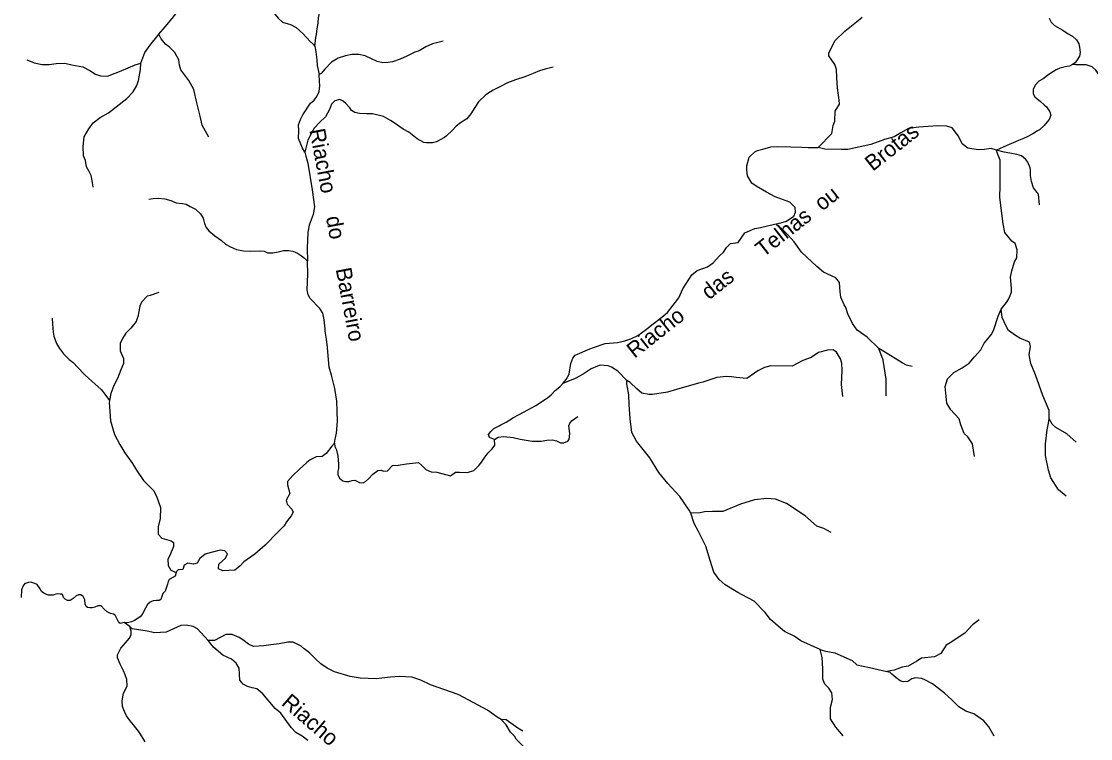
# Model space of a CAD drawing. Extents: x 717.8 to 772.7, y 8672.2 to 8728.
# Drawn here: x 731.77 to 745.36, y 8693.87 to 8702.99 of the extents above; entities that cross this region are included whole.
import ezdxf
from ezdxf.enums import TextEntityAlignment as Align

# ---------------------------------------------------------------- set-up
doc = ezdxf.new("R2010")
doc.units = 0
doc.header["$LTSCALE"] = 0.08
doc.linetypes.add('LONG_DASHED', pattern=[7.5, 6, -1.5])
doc.layers.add('61', color=7, linetype='Continuous')
doc.layers.add('9', color=7, linetype='LONG_DASHED', lineweight=25)

msp = doc.modelspace()

# ---------------------------------------------------------------- linework, layer by layer
at = {"layer": '9'}
msp.add_line((733.1514, 8695.2936), (733.0803, 8695.3465), dxfattribs=at)
for points in [[(734.3526, 8703.6392), (734.4907, 8703.6359), (734.5619, 8703.6114), (734.6403, 8703.5631), (734.6934, 8703.4998), (734.7153, 8703.458), (734.748, 8703.3878), (734.7584, 8703.3394), (734.7952, 8703.2871), (734.8925, 8703.2294), (734.9722, 8703.1152), (734.999, 8703.074), (735.0368, 8703.0274), (735.0933, 8702.9779), (735.1917, 8702.9464), (735.2674, 8702.9086), (735.3517, 8702.8327), (735.4443, 8702.732), (735.485, 8702.6924), (735.5037, 8702.6658)], [(733.5186, 8702.8226), (733.5988, 8702.9187), (733.6899, 8703.0208), (733.7896, 8703.1523), (733.8096, 8703.2191), (733.8242, 8703.2836), (733.8553, 8703.3552), (733.8781, 8703.4006), (733.8984, 8703.4386)], [(735.5037, 8702.6658), (735.5152, 8702.7801), (735.5234, 8702.8207), (735.5272, 8702.8636), (735.5439, 8702.9663), (735.5511, 8703.0307), (735.5654, 8703.1071), (735.575, 8703.1668), (735.5893, 8703.2169)], [(741.9017, 8701.382), (742.073, 8701.5613), (742.0908, 8701.6619), (742.1132, 8701.7189), (742.1183, 8701.8464), (742.1712, 8701.9324), (742.1677, 8701.9855), (742.1445, 8702.1431), (742.1393, 8702.2679), (742.1346, 8702.3753), (742.1111, 8702.4397), (742.038, 8702.5475), (742.0381, 8702.5881), (742.1166, 8702.7432), (742.2394, 8702.862), (742.3859, 8702.9814), (742.4606, 8703.0389)], [(744.8368, 8703.0256), (744.8631, 8702.9778), (744.906, 8702.9348), (745.011, 8702.8764), (745.0777, 8702.8287), (745.1325, 8702.8001), (745.185, 8702.7522), (745.2136, 8702.6998), (745.2232, 8702.6592), (745.2304, 8702.5923), (745.2233, 8702.5422), (745.1924, 8702.4967), (745.1663, 8702.4609), (745.1353, 8702.437)], [(733.2909, 8702.4534), (733.343, 8702.591), (733.386, 8702.652), (733.4204, 8702.7006), (733.494, 8702.7882), (733.5186, 8702.8226)], [(734.1573, 8701.5136), (734.0718, 8701.667), (734.0433, 8701.7806), (734.0034, 8701.951), (733.9636, 8702.1214), (733.9009, 8702.235), (733.7984, 8702.3714), (733.7813, 8702.4282), (733.7756, 8702.4964), (733.722, 8702.5898), (733.6522, 8702.6621), (733.6063, 8702.6981), (733.5491, 8702.7653), (733.5186, 8702.8226)], [(735.5037, 8702.6658), (735.5049, 8702.651), (735.5142, 8702.6003), (735.5274, 8702.4989), (735.5329, 8702.4256), (735.5561, 8702.3102)], [(737.1338, 8702.7343), (736.9964, 8702.7011), (736.9143, 8702.6606), (736.8287, 8702.6125), (736.7741, 8702.5945), (736.6733, 8702.543), (736.5854, 8702.5042), (736.4916, 8702.4721), (736.4363, 8702.4617), (736.368, 8702.4573), (736.296, 8702.4756), (736.2226, 8702.51), (736.143, 8702.5484), (736.0625, 8702.5646), (735.9714, 8702.5646), (735.891, 8702.5486), (735.7999, 8702.5165), (735.7141, 8702.4684)], [(731.8406, 8702.4992), (731.9369, 8702.4613), (732.0387, 8702.4374), (732.1261, 8702.4402), (732.2148, 8702.4528), (732.3233, 8702.4546), (732.4142, 8702.4357), (732.5518, 8702.4102), (732.6419, 8702.3616), (732.716, 8702.3161), (732.7789, 8702.2923), (732.8677, 8702.2909), (732.9666, 8702.3271), (733.0209, 8702.3488), (733.0998, 8702.3836), (733.2204, 8702.4344), (733.2909, 8702.4534)], [(732.6857, 8700.8783), (732.6714, 8700.9648), (732.6591, 8701.0272), (732.6339, 8701.0763), (732.6016, 8701.1389), (732.5858, 8701.2184), (732.5624, 8701.2766), (732.56, 8701.3963), (732.5722, 8701.5169), (732.6302, 8701.6216), (732.6862, 8701.6973), (732.7727, 8701.7651), (732.8808, 8701.8258), (733.1145, 8702.0073), (733.1942, 8702.0923), (733.2414, 8702.1698), (733.2626, 8702.2342), (733.2853, 8702.3742), (733.2909, 8702.4534)], [(738.5331, 8702.4024), (738.4288, 8702.3773), (738.3593, 8702.3558), (738.279, 8702.3237), (738.172, 8702.2808), (738.0544, 8702.2433), (737.9527, 8702.2057), (737.8618, 8702.1575), (737.7676, 8702.1114), (737.7337, 8702.0905), (737.6783, 8702.0539), (737.582, 8701.963), (737.5359, 8701.8932), (737.4865, 8701.8099), (737.4345, 8701.7462), (737.356, 8701.6974), (737.3001, 8701.6531), (737.2543, 8701.6026), (737.1759, 8701.5311), (737.1504, 8701.5095), (737.0501, 8701.4566), (736.9965, 8701.4441), (736.9219, 8701.4426), (736.8878, 8701.4465), (736.8016, 8701.4938), (736.6975, 8701.5762), (736.626, 8701.6174), (736.5103, 8701.6974), (736.463, 8701.7261), (736.3738, 8701.7768), (736.2343, 8701.8095), (736.1647, 8701.8096), (736.0717, 8701.8138), (736.0104, 8701.827), (735.97, 8701.8551), (735.9475, 8701.8892), (735.8986, 8701.9404), (735.8644, 8701.9738), (735.8225, 8701.9924), (735.7581, 8701.9745), (735.7162, 8701.9333), (735.6912, 8701.8674), (735.6369, 8701.7727), (735.5662, 8701.7066), (735.4938, 8701.6282), (735.473, 8701.5905), (735.4129, 8701.4761), (735.3764, 8701.3226)], [(735.7141, 8702.4684), (735.6282, 8702.3775), (735.5846, 8702.3255), (735.5561, 8702.3102)], [(745.1353, 8702.437), (745.0964, 8702.4182), (745.04, 8702.4098), (744.9715, 8702.39), (744.9266, 8702.3687), (744.8923, 8702.3481), (744.8314, 8702.3108), (744.7616, 8702.2578), (744.7045, 8702.2242), (744.664, 8702.1789), (744.6316, 8702.1246), (744.6331, 8702.0667), (744.6552, 8702.0264), (744.7264, 8701.9675), (744.7741, 8701.9246), (744.8037, 8701.9014), (744.8456, 8701.8374), (744.857, 8701.7948), (744.8387, 8701.7407), (744.8128, 8701.7087), (744.7725, 8701.6607), (744.7126, 8701.6069), (744.6872, 8701.5936), (744.6301, 8701.5578), (744.5592, 8701.519), (744.512, 8701.4984), (744.4488, 8701.4731), (744.4083, 8701.4563), (744.2991, 8701.4066), (744.1662, 8701.348)], [(745.5158, 8702.2419), (745.488, 8702.2772), (745.4514, 8702.3382), (745.4285, 8702.3657), (745.3813, 8702.4083), (745.3059, 8702.4335), (745.2806, 8702.4323), (745.221, 8702.4346), (745.1758, 8702.4346), (745.1353, 8702.437)], [(735.3764, 8701.3226), (735.3477, 8701.3732), (735.2965, 8701.4982), (735.2983, 8701.601), (735.2968, 8701.6699), (735.321, 8701.7372), (735.3497, 8701.7989), (735.4487, 8701.9448), (735.4941, 8701.983), (735.5299, 8702.0307), (735.5585, 8702.0928), (735.5656, 8702.1668), (735.5607, 8702.2265), (735.5561, 8702.3102)], [(744.1662, 8701.348), (744.1001, 8701.3702), (744.0112, 8701.3561), (743.9343, 8701.355), (743.8042, 8701.3756), (743.7305, 8701.4309), (743.6828, 8701.5276), (743.6047, 8701.6315), (743.5354, 8701.6554), (743.4205, 8701.6586), (743.3002, 8701.6521), (743.1798, 8701.6424), (743.0497, 8701.6228), (742.9511, 8701.5697), (742.8677, 8701.5187), (742.7441, 8701.4829), (742.5717, 8701.4233), (742.3755, 8701.3778), (742.278, 8701.3593), (742.193, 8701.356), (741.9872, 8701.3633), (741.9017, 8701.382)], [(735.3764, 8701.3226), (735.3892, 8701.2736), (735.4148, 8701.1835), (735.4697, 8700.8462), (735.4979, 8700.6298), (735.4825, 8700.5332), (735.4297, 8700.3971), (735.4126, 8700.3064), (735.4068, 8700.0981), (735.4096, 8699.9372)], [(741.3648, 8700.4115), (741.427, 8700.4254), (741.4991, 8700.4471), (741.5911, 8700.5099), (741.6137, 8700.5614), (741.6078, 8700.6199), (741.5389, 8700.687), (741.4475, 8700.721), (741.3523, 8700.7579), (741.2439, 8700.8143), (741.111, 8700.8905), (741.0587, 8700.9304), (741.0008, 8701.0216), (740.9949, 8701.099), (740.9917, 8701.1504), (741.0215, 8701.2603), (741.0971, 8701.328), (741.128, 8701.3435), (741.1987, 8701.3622), (741.3009, 8701.3896), (741.3854, 8701.3964), (741.5521, 8701.3932), (741.692, 8701.387), (741.7727, 8701.3817), (741.829, 8701.3821), (741.9017, 8701.382)], [(744.7119, 8700.6555), (744.7019, 8700.7878), (744.6389, 8700.8724), (744.6121, 8700.95), (744.5994, 8701.0271), (744.5984, 8701.1052), (744.5945, 8701.126), (744.5671, 8701.197), (744.5397, 8701.2311), (744.4861, 8701.2782), (744.4255, 8701.2927), (744.3376, 8701.3113), (744.2661, 8701.3247), (744.1662, 8701.348)], [(744.2261, 8699.3296), (744.2962, 8699.4143), (744.324, 8699.4612), (744.3566, 8699.5427), (744.3596, 8699.5948), (744.3473, 8699.7341), (744.3607, 8699.8174), (744.3981, 8699.9306), (744.4237, 8699.9822), (744.4295, 8700.083), (744.4046, 8700.1632), (744.3639, 8700.1909), (744.272, 8700.3007), (744.2501, 8700.4119), (744.2097, 8700.7486), (744.2148, 8700.8957), (744.2119, 8701.0966), (744.2126, 8701.2236), (744.1816, 8701.3058), (744.1662, 8701.348)], [(733.3918, 8700.7246), (733.448, 8700.7339), (733.5159, 8700.7385), (733.5955, 8700.729), (733.6704, 8700.7078), (733.7384, 8700.6796), (733.8203, 8700.6725), (733.8671, 8700.6631), (733.9186, 8700.6349), (733.9866, 8700.5997), (734.0475, 8700.5386), (734.0826, 8700.4846), (734.0989, 8700.4168), (734.1223, 8700.3675), (734.1574, 8700.3253), (734.2323, 8700.2595), (734.3143, 8700.2009), (734.368, 8700.156), (734.4313, 8700.1188), (734.5062, 8700.0881), (734.5975, 8700.0693), (734.6794, 8700.0645), (734.7954, 8700.0714), (734.8608, 8700.0666), (734.903, 8700.0456), (734.9685, 8700.0431), (735.0387, 8700.0571), (735.1042, 8700.0757), (735.1698, 8700.0757), (735.2236, 8700.0662), (735.282, 8700.0404), (735.3335, 8700.0075), (735.3732, 8699.9747), (735.4096, 8699.9372)], [(738.6562, 8698.3854), (738.6955, 8698.4346), (738.7367, 8698.5035), (738.7566, 8698.6384), (738.7841, 8698.704), (738.8104, 8698.7453), (738.9989, 8698.8256), (739.0452, 8698.8429), (739.1914, 8698.8903), (739.3489, 8698.906), (739.4436, 8698.9263), (739.521, 8698.9528), (739.608, 8698.9933), (739.7009, 8699.0628), (739.8035, 8699.1423), (739.8939, 8699.2096), (739.9834, 8699.2867), (740.1277, 8699.4728), (740.1786, 8699.5878), (740.2951, 8699.7631), (740.3625, 8699.8178), (740.4936, 8699.8665), (740.5674, 8699.9161), (740.6463, 8700.0042), (740.6973, 8700.0514), (740.7362, 8700.1112), (740.788, 8700.1619), (740.8824, 8700.175), (740.9669, 8700.3005), (741.0934, 8700.354), (741.1668, 8700.3661), (741.3467, 8700.4065), (741.3648, 8700.4115)], [(742.6698, 8698.8286), (742.523, 8698.9722), (742.395, 8699.0599), (742.3359, 8699.1473), (742.2782, 8699.267), (742.2507, 8699.351), (742.2321, 8699.383), (742.1894, 8699.48), (742.1793, 8699.5472), (742.1708, 8699.6656), (742.1271, 8699.7269), (741.9702, 8699.7968), (741.8819, 8699.8708), (741.6902, 8700.0508), (741.5973, 8700.1843), (741.5211, 8700.2707), (741.4511, 8700.3372), (741.3886, 8700.3876), (741.3648, 8700.4115)], [(735.7515, 8697.6241), (735.7632, 8697.6753), (735.7767, 8697.752), (735.7891, 8697.8989), (735.7868, 8698.0302), (735.7837, 8698.1607), (735.7584, 8698.3192), (735.7131, 8698.4892), (735.6848, 8698.5913), (735.6736, 8698.7329), (735.6625, 8698.8407), (735.6512, 8698.9483), (735.6336, 8699.0487), (735.6336, 8699.0771), (735.6223, 8699.1905), (735.6054, 8699.2755), (735.5657, 8699.3379), (735.4444, 8699.4658), (735.4164, 8699.5101), (735.404, 8699.5745), (735.4156, 8699.7719), (735.4096, 8699.9372)], [(733.5188, 8699.5418), (733.4076, 8699.5007), (733.3708, 8699.4935), (733.3, 8699.419), (733.2762, 8699.3642), (733.2661, 8699.2984), (733.2581, 8699.2456), (733.2334, 8699.1727), (733.1619, 8699.0846), (733.0998, 8699.0246), (733.0565, 8698.9538), (733.0276, 8698.8917), (733.0276, 8698.7992), (733.0713, 8698.7025), (733.0707, 8698.6376), (733.0389, 8698.5581), (732.9927, 8698.4484), (732.9472, 8698.3588), (732.9076, 8698.257), (732.8927, 8698.1679)], [(743.8879, 8697.4565), (743.8632, 8697.6185), (743.8049, 8697.7036), (743.7561, 8697.7469), (743.7149, 8697.8594), (743.6937, 8697.9351), (743.5852, 8698.0483), (743.5375, 8698.1325), (743.5139, 8698.347), (743.5427, 8698.4438), (743.6237, 8698.5248), (743.7308, 8698.5804), (743.8194, 8698.6422), (743.8887, 8698.7205), (743.9662, 8698.8111), (744.0108, 8698.8943), (744.0999, 8699.0019), (744.1275, 8699.0563), (744.1893, 8699.2403), (744.2261, 8699.3296)], [(744.835, 8697.9336), (744.8351, 8698.0411), (744.7544, 8698.2327), (744.6637, 8698.4948), (744.6032, 8698.636), (744.5831, 8698.7469), (744.5982, 8698.8535), (744.5869, 8698.9076), (744.4619, 8698.9587), (744.4107, 8698.9945), (744.3195, 8699.0568), (744.2886, 8699.1127), (744.2398, 8699.2212), (744.2261, 8699.3296)], [(732.1623, 8699.2135), (732.167, 8699.1385), (732.1717, 8699.0846), (732.1779, 8699.0362), (732.1864, 8698.9836), (732.2177, 8698.8899), (732.2582, 8698.827), (732.3067, 8698.7588), (732.3815, 8698.6884), (732.4314, 8698.6514), (732.4922, 8698.5857), (732.5765, 8698.4991), (732.628, 8698.4475), (732.7052, 8698.3773), (732.7849, 8698.3075), (732.8339, 8698.2484), (732.8927, 8698.1679)], [(742.2152, 8698.2202), (742.1969, 8698.3726), (742.2041, 8698.5478), (742.1995, 8698.6413), (742.184, 8698.6981), (742.1356, 8698.7837), (742.0892, 8698.8105), (742.018, 8698.806), (741.9056, 8698.7765), (741.8108, 8698.7131), (741.7076, 8698.6759), (741.5691, 8698.6026), (741.2994, 8698.6071), (741.2196, 8698.5883), (741.1332, 8698.5443), (740.9953, 8698.4469), (740.8581, 8698.4606), (740.7974, 8698.4665), (740.7361, 8698.4739), (740.6139, 8698.4582), (740.4343, 8698.3994), (740.3951, 8698.3922), (740.2603, 8698.3518), (740.0983, 8698.3051), (739.9872, 8698.2711), (739.7958, 8698.2456), (739.7474, 8698.245), (739.6602, 8698.2586), (739.5939, 8698.3143), (739.5122, 8698.3953), (739.4701, 8698.4196)], [(742.7661, 8698.2261), (742.765, 8698.4404), (742.7274, 8698.6801), (742.6698, 8698.8286)], [(743.0957, 8698.5988), (743.0242, 8698.6158), (742.967, 8698.6472), (742.735, 8698.7885), (742.6698, 8698.8286)], [(739.4701, 8698.4196), (739.3545, 8698.541), (739.2757, 8698.5915), (739.2307, 8698.6077), (739.1295, 8698.6149), (739.0975, 8698.6025), (739.0158, 8698.5685), (738.9143, 8698.5029), (738.8115, 8698.447), (738.6562, 8698.3854)], [(737.7844, 8697.6697), (737.723, 8697.6981), (737.7086, 8697.7362), (737.7398, 8697.7751), (737.7798, 8697.812), (737.8437, 8697.8468), (737.8669, 8697.8584), (737.9365, 8697.8932), (738.0293, 8697.951), (738.157, 8698.0206), (738.3137, 8698.1016), (738.4589, 8698.2), (738.5053, 8698.2406), (738.5575, 8698.2927), (738.6169, 8698.3429), (738.6562, 8698.3854)], [(740.2808, 8696.735), (740.2607, 8696.775), (740.1432, 8696.9459), (739.9917, 8697.1117), (739.8771, 8697.2539), (739.761, 8697.4404), (739.5929, 8697.6483), (739.5303, 8697.7614), (739.5106, 8697.9356), (739.5001, 8698.1173), (739.492, 8698.2378), (739.4697, 8698.377), (739.4701, 8698.4196)], [(732.8927, 8698.1679), (732.8878, 8698.1417), (732.9059, 8697.9087), (732.9578, 8697.7368), (733.0243, 8697.609), (733.0884, 8697.5017), (733.1848, 8697.3657), (733.2371, 8697.2802), (733.3252, 8697.1502), (733.4198, 8697.0577), (733.4517, 8697.0224), (733.4901, 8696.9525), (733.5409, 8696.8086), (733.5371, 8696.6673), (733.5097, 8696.5596), (733.5112, 8696.4676), (733.5581, 8696.417), (733.6772, 8696.3838), (733.7075, 8696.3632), (733.7054, 8696.3101), (733.6602, 8696.1987), (733.6362, 8696.1507), (733.6382, 8696.0697), (733.671, 8696.0094), (733.7395, 8695.9809)], [(737.7844, 8697.6697), (737.8335, 8697.7002), (737.9066, 8697.7111), (738.022, 8697.6979), (738.1141, 8697.6773), (738.2642, 8697.6514), (738.3791, 8697.6499), (738.4522, 8697.6628), (738.5223, 8697.6666), (738.5762, 8697.6544), (738.6242, 8697.6308), (738.6684, 8697.6293), (738.7171, 8697.6498), (738.7367, 8697.6729), (738.7422, 8697.7489), (738.73, 8697.8456), (738.7445, 8697.8776), (738.7734, 8697.9126), (738.8466, 8697.9622)], [(745.0517, 8696.9496), (744.9562, 8697.0298), (744.8588, 8697.186), (744.8294, 8697.2809), (744.7895, 8697.4665), (744.7894, 8697.6174), (744.8121, 8697.7944), (744.8293, 8697.8794), (744.835, 8697.9336)], [(745.1806, 8697.6361), (745.0603, 8697.7451), (744.9194, 8697.8226), (744.8728, 8697.8659), (744.835, 8697.9336)], [(735.7515, 8697.6241), (735.7574, 8697.5845), (735.7774, 8697.5407), (735.793, 8697.46), (735.8026, 8697.3636), (735.8025, 8697.3013), (735.7968, 8697.2673), (735.797, 8697.227), (735.8164, 8697.178), (735.8591, 8697.1469), (735.8909, 8697.1368), (735.936, 8697.1392), (735.9787, 8697.1524), (736.0113, 8697.1547), (736.0694, 8697.1231), (736.115, 8697.1224), (736.1473, 8697.1378), (736.1837, 8697.1734), (736.2404, 8697.2316), (736.3047, 8697.2777), (736.3469, 8697.2798), (736.3771, 8697.2711), (736.4275, 8697.2727), (736.4891, 8697.3418), (736.564, 8697.3446), (736.6698, 8697.3642), (736.8201, 8697.3799), (736.8593, 8697.3433), (736.9116, 8697.2923), (736.9808, 8697.2622), (737.0553, 8697.2583), (737.2252, 8697.2112), (737.2898, 8697.2572), (737.3416, 8697.2572), (737.4451, 8697.2533), (737.5254, 8697.2778), (737.5868, 8697.3396), (737.613, 8697.3693), (737.6537, 8697.4325), (737.7007, 8697.4986), (737.7559, 8697.551), (737.7893, 8697.6014), (737.7844, 8697.6697)], [(735.7515, 8697.6241), (735.72, 8697.5858), (735.6485, 8697.4918), (735.5965, 8697.4561), (735.5197, 8697.4517), (735.4452, 8697.4146), (735.4006, 8697.3776), (735.3036, 8697.2886), (735.2217, 8697.2145), (735.1567, 8697.1385), (735.1554, 8697.0942), (735.1844, 8696.9847), (735.1403, 8696.9001), (735.1492, 8696.8484), (735.2118, 8696.7871), (735.2289, 8696.7475), (735.2009, 8696.7005), (735.1417, 8696.6236), (735.1118, 8696.5759), (735.0301, 8696.4887), (734.8701, 8696.3285), (734.7414, 8696.2134), (734.5984, 8696.1187), (734.55, 8696.0611), (734.4847, 8696.012), (734.3328, 8696.0011), (734.277, 8696.027), (734.2824, 8696.0869), (734.3652, 8696.1633), (734.3907, 8696.2198), (734.36, 8696.2579), (734.2974, 8696.2641), (734.1837, 8696.2341), (734.1098, 8696.2145), (734.042, 8696.1585), (734.0059, 8696.0999), (733.9603, 8696.087), (733.8896, 8696.0997), (733.8434, 8696.0737), (733.8241, 8696.0182), (733.7647, 8696.0166), (733.7481, 8696), (733.7395, 8695.9809)], [(742.0645, 8696.4905), (741.9706, 8696.542), (741.8845, 8696.5694), (741.7357, 8696.7006), (741.4988, 8696.8587), (741.3579, 8696.9128), (741.2477, 8696.9223), (741.0911, 8696.9053), (740.9117, 8696.8479), (740.688, 8696.7561), (740.6017, 8696.7558), (740.5588, 8696.7559), (740.4549, 8696.754), (740.4017, 8696.7403), (740.2808, 8696.735)], [(741.9274, 8695.0029), (741.6789, 8695.1105), (741.5964, 8695.1729), (741.4716, 8695.2297), (741.3936, 8695.2989), (741.2955, 8695.3824), (741.2253, 8695.4727), (741.086, 8695.6187), (740.935, 8695.696), (740.8814, 8695.7281), (740.7205, 8695.8227), (740.6403, 8695.893), (740.5734, 8695.9833), (740.528, 8696.1341), (740.4745, 8696.3158), (740.3796, 8696.5007), (740.3261, 8696.6033), (740.2808, 8696.735)], [(733.7395, 8695.9809), (733.7255, 8695.9361), (733.6498, 8695.8913), (733.6387, 8695.8657), (733.6297, 8695.832), (733.6023, 8695.7446), (733.5727, 8695.7136), (733.5455, 8695.6392), (733.5246, 8695.6255), (733.4911, 8695.6262), (733.4471, 8695.6189), (733.4249, 8695.6127), (733.4102, 8695.6054), (733.3775, 8695.575), (733.3485, 8695.5293), (733.3265, 8695.4817), (733.316, 8695.4586), (733.2818, 8695.4185), (733.2124, 8695.3696), (733.1718, 8695.3548), (733.1203, 8695.3432), (733.0803, 8695.3465)], [(733.0803, 8695.3465), (733.0271, 8695.3332), (733.0108, 8695.345), (733.0045, 8695.3626), (732.9737, 8695.4237), (732.9638, 8695.4391), (732.9431, 8695.4533), (732.9034, 8695.4583), (732.8611, 8695.4826), (732.8267, 8695.515), (732.7847, 8695.5572), (732.7612, 8695.5585), (732.7427, 8695.5563), (732.7083, 8695.5414), (732.6721, 8695.5314), (732.6423, 8695.5319), (732.612, 8695.5377), (732.5957, 8695.5477), (732.5844, 8695.5789), (732.5772, 8695.633), (732.5709, 8695.6524), (732.5577, 8695.6773), (732.5288, 8695.6976), (732.4967, 8695.6972), (732.4691, 8695.685), (732.4325, 8695.6488), (732.3945, 8695.623), (732.3579, 8695.6239), (732.328, 8695.6402), (732.3068, 8695.6653), (732.2968, 8695.6995), (732.2864, 8695.7053), (732.2647, 8695.7071), (732.2376, 8695.7099), (732.2115, 8695.7039), (732.1781, 8695.6946), (732.1451, 8695.691), (732.1173, 8695.6909), (732.0935, 8695.7009), (732.0581, 8695.7162), (732.0265, 8695.7389), (732.0095, 8695.772), (731.9735, 8695.829), (731.9445, 8695.842), (731.8935, 8695.857), (731.8622, 8695.8558), (731.8365, 8695.8448), (731.8175, 8695.84), (731.7955, 8695.812), (731.7741, 8695.7607), (731.7696, 8695.6629)], [(743.9483, 8695.3779), (743.8641, 8695.3151), (743.7642, 8695.2107), (743.577, 8695.0885), (743.5291, 8695.0563), (743.4609, 8694.9495), (743.3786, 8694.9107), (743.2149, 8694.8925), (743.1556, 8694.8557), (743.0461, 8694.7897), (742.9681, 8694.7785), (742.8667, 8694.7376), (742.773, 8694.7245)], [(733.3466, 8693.8285), (733.2751, 8693.9465), (733.1978, 8694.0458), (733.1539, 8694.0939), (733.1067, 8694.1573), (733.0815, 8694.2143), (733.0579, 8694.2762), (733.0558, 8694.3496), (733.0696, 8694.4454), (733.1152, 8694.5358), (733.1128, 8694.6213), (733.0916, 8694.6782), (733.0695, 8694.7328), (733.0298, 8694.8141), (732.9937, 8694.8963), (732.9956, 8694.9354), (733.035, 8695.0202), (733.0968, 8695.0887), (733.1475, 8695.1476), (733.1686, 8695.1943), (733.1664, 8695.2359), (733.1514, 8695.2936)], [(734.1474, 8695.1163), (734.0127, 8695.2644), (733.9551, 8695.2935), (733.8689, 8695.3133), (733.7995, 8695.3068), (733.6141, 8695.2235), (733.4673, 8695.2137), (733.3709, 8695.2359), (733.181, 8695.2637), (733.1514, 8695.2936)], [(737.8695, 8694.1113), (737.8202, 8694.1419), (737.6973, 8694.2314), (737.4598, 8694.36), (737.3246, 8694.429), (736.9734, 8694.5538), (736.849, 8694.6116), (736.7367, 8694.6515), (736.5781, 8694.6588), (736.4642, 8694.649), (736.2844, 8694.6279), (736.0789, 8694.6378), (735.9536, 8694.6597), (735.7519, 8694.7192), (735.6591, 8694.7647), (735.5788, 8694.8183), (735.5104, 8694.8834), (735.434, 8694.9583), (735.3656, 8695.012), (735.329, 8695.0454), (735.2265, 8695.0975), (735.1582, 8695.0959), (735.0473, 8695.0761), (734.9454, 8695.0635), (734.8563, 8695.0508), (734.7222, 8695.0389), (734.6595, 8695.069), (734.5888, 8695.1268), (734.5426, 8695.1542), (734.4518, 8695.1916), (734.3732, 8695.1931), (734.2272, 8695.1158), (734.1474, 8695.1163)], [(735.4123, 8693.8453), (735.342, 8693.9019), (735.2611, 8693.949), (735.2038, 8694.0108), (735.0708, 8694.1921), (735.0006, 8694.2508), (734.8418, 8694.4394), (734.767, 8694.5028), (734.7082, 8694.5165), (734.6464, 8694.5326), (734.5922, 8694.5608), (734.5503, 8694.6112), (734.5427, 8694.7654), (734.5045, 8694.8296), (734.4442, 8694.8777), (734.3334, 8694.9299), (734.2209, 8695.0256), (734.1793, 8695.0753), (734.1474, 8695.1163)], [(742.2183, 8693.9043), (742.1262, 8694.0147), (742.0578, 8694.1206), (742.0589, 8694.27), (742.0845, 8694.3659), (742.0745, 8694.4506), (742.0344, 8694.5108), (741.9865, 8694.561), (741.9609, 8694.6234), (741.9597, 8694.7549), (741.9522, 8694.9008), (741.9274, 8695.0029)], [(741.9274, 8695.0029), (741.9756, 8694.987), (742.1112, 8694.9578), (742.3318, 8694.8618), (742.3941, 8694.8062), (742.5541, 8694.773), (742.773, 8694.7245)], [(744.136, 8693.9002), (744.0714, 8694.0192), (744.0044, 8694.0969), (743.8784, 8694.1847), (743.7764, 8694.2177), (743.6901, 8694.2725), (743.5992, 8694.3611), (743.5076, 8694.4467), (743.3553, 8694.5652), (743.2458, 8694.6208), (743.2128, 8694.6343), (743.1377, 8694.6419), (743.0913, 8694.6275), (743.0417, 8694.5938), (742.9809, 8694.5908), (742.9441, 8694.6021), (742.887, 8694.6444), (742.8373, 8694.6906), (742.8168, 8694.7082), (742.773, 8694.7245)], [(738.3015, 8693.1977), (738.2982, 8693.3556), (738.304, 8693.3504), (738.2982, 8693.5135), (738.2535, 8693.6405), (738.2193, 8693.6999), (738.178, 8693.7479), (738.06, 8693.8635), (738.0418, 8693.8992), (737.9893, 8693.9514), (737.9339, 8694.0442), (737.8695, 8694.1113)], [(738.1463, 8693.9661), (738.0849, 8694.001), (737.9348, 8694.1069), (737.8695, 8694.1113)]]:
    msp.add_lwpolyline(points, dxfattribs=at)

# ---------------------------------------------------------------- texts
at = {"layer": '61'}
for s, rotation, p in [('Riacho    do     Barreiro', 280.706, (735.6883, 8700.2543)), ('Riacho     das      Telhas  ou       Brotas', 38.138, (741.384, 8700.1235)), ('Riacho    do        Mocambo', 319.253, (736.2762, 8693.2622))]:
    msp.add_text(s, height=0.2, rotation=rotation, dxfattribs=at).set_placement(p, align=Align.CENTER)

doc.saveas('drawing.dxf')
